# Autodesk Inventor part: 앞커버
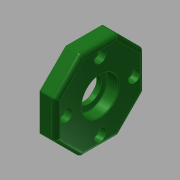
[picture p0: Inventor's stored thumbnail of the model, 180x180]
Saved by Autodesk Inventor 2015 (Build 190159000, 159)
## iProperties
Created: 2015-11
Part Number: 앞커버
Material: 알루미늄 6061
Document SubType Name: Modeling
Designer: mduedu
Density: 1 g/cm^3
Appearance: 매끄러움 - 짙은 산림 녹색
Author: mduedu
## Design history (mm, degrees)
sketch "스케치5" dims "d66" = 60
  geometry: L1 (12.426, 30)-(30, 12.426); L2 (30, 12.426)-(30, -12.426); L3 (30, -12.426)-(12.426, -30); L4 (12.426, -30)-(-12.426, -30); L5 (-12.426, -30)-(-30, -12.426); L6 (-30, -12.426)-(-30, 12.426); L7 (-30, 12.426)-(-12.426, 30); L8 (-12.426, 30)-(12.426, 30); 4 further points
  constraints: 16 end point, 2 coincident, 2 vertical alignment, 1 midpoint, 19 other
extrude "돌출2" new body sketch "스케치5" distance "d67" = 11; taper "d68" = 0 deg
sketch "스케치6"
  geometry: C1 r 16 at (0, 0); 1 further point
  constraints: 1 centre point, 1 coincident
  dimensions: "d69" = 32 diameter of C1
extrude "돌출3" join sketch "스케치6" distance "d70" = 3; taper "d71" = 0 deg
hole "구멍7" diameter "d98" = 25; stored, may be unused: countersink angle "d102" = 90 deg, drill point angle "d104" = 0 deg; dims "d96" = 10, "d97" = 10, "d99" = 6, "d100" = 4, "d101" = 2, "d103" = 3
hole "구멍8" diameter "d107" = 25; stored, may be unused: countersink angle "d111" = 90 deg, drill point angle "d113" = 0 deg; dims "d105" = 10, "d106" = 10, "d108" = 6, "d109" = 4, "d110" = 2, "d112" = 7.7
hole "구멍9" diameter "d116" = 17; stored, may be unused: countersink angle "d120" = 90 deg, drill point angle "d122" = 0 deg; dims "d114" = 10, "d115" = 10, "d117" = 6, "d118" = 4, "d119" = 2, "d121" = 7.7
chamfer "모따기2" distance "d123" = 0.6; stored, may be unused: second distance "d124" = 2, angle "d125" = 30 deg
fillet "모깎기11" dims "d126" = 0.3
fillet "모깎기12" dims "d127" = 1
fillet "모깎기13" dims "d128" = 3
fillet "모깎기14" dims "d129" = 3
fillet "모깎기15" dims "d130" = 0.3
sketch "스케치8" dims "d131" = 46
  geometry: 3 further points
  constraints: 2 vertical alignment, 1 coincident, 2 other
hole "구멍10" sketch "스케치8" at (0, 23) diameter "d132" = 4.5; stored, may be unused: countersink angle "d136" = 90 deg, drill point angle "d138" = 0 deg; dims "d133" = 6, "d134" = 8, "d135" = 4.6, "d137" = 7.7
node "솔리드2"
pattern_circular "원형 패턴4" dims angle "d140" = 360 deg
